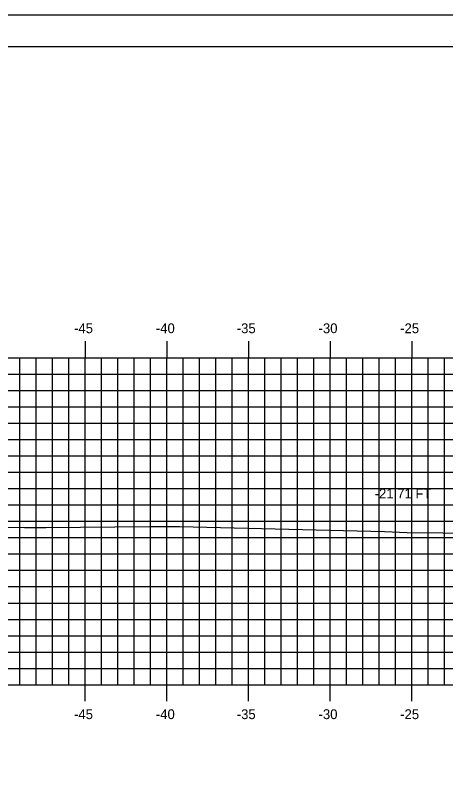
# Model space of a CAD drawing. Extents: x 1147633 to 1147803, y 608981 to 609091.
# Drawn here: x 1147667.17 to 1147693.53, y 609044.65 to 609091.28 of the extents above; entities that cross this region are included whole.
import ezdxf

# ---------------------------------------------------------------- set-up
doc = ezdxf.new("R2010")
doc.units = 0
for name, color, linetype in [('BORDER', 7, 'Continuous'), ('D_Text_Standard', 7, 'Continuous'), ('H_V ANNOTATION', 7, 'Continuous'), ('MAJOR', 7, 'Continuous'), ('MINOR', 7, 'Continuous'), ('PLOT BOUNDARY', 7, 'Continuous'), ('S_Roadway_Centerline', 7, 'Continuous')]:
    doc.layers.add(name, color=color, linetype=linetype)

msp = doc.modelspace()

# ---------------------------------------------------------------- linework, layer by layer
at = {"layer": 'BORDER'}
msp.add_lwpolyline([(1147641.454, 608984.335), (1147801.454, 608984.335), (1147801.454, 609089.335), (1147641.454, 609089.335)], close=True, dxfattribs=at)
at = {"layer": 'MAJOR'}
for p, q in [((1147671.454, 609071.337), (1147671.454, 609070.335)), ((1147676.454, 609071.337), (1147676.454, 609070.335)), ((1147681.454, 609071.337), (1147681.454, 609070.335)), ((1147686.454, 609071.337), (1147686.454, 609070.335)), ((1147691.454, 609071.337), (1147691.454, 609070.335)), ((1147646.454, 609070.335), (1147786.454, 609070.335)), ((1147646.454, 609070.335), (1147786.454, 609070.335)), ((1147671.454, 609050.335), (1147671.454, 609070.335)), ((1147676.454, 609050.335), (1147676.454, 609070.335)), ((1147681.454, 609050.335), (1147681.454, 609070.335)), ((1147686.454, 609050.335), (1147686.454, 609070.335)), ((1147691.454, 609050.335), (1147691.454, 609070.335)), ((1147646.454, 609065.335), (1147786.454, 609065.335)), ((1147646.454, 609060.335), (1147786.454, 609060.335)), ((1147646.454, 609055.335), (1147786.454, 609055.335)), ((1147646.454, 609050.335), (1147786.454, 609050.335)), ((1147646.454, 609050.335), (1147786.454, 609050.335)), ((1147671.454, 609049.333), (1147671.454, 609050.335)), ((1147676.454, 609049.333), (1147676.454, 609050.335)), ((1147681.454, 609049.333), (1147681.454, 609050.335)), ((1147686.454, 609049.333), (1147686.454, 609050.335)), ((1147691.454, 609049.333), (1147691.454, 609050.335))]:
    msp.add_line(p, q, dxfattribs=at)
at = {"layer": 'MINOR'}
for p, q in [((1147667.454, 609050.335), (1147667.454, 609070.335)), ((1147668.454, 609050.335), (1147668.454, 609070.335)), ((1147669.454, 609050.335), (1147669.454, 609070.335)), ((1147670.454, 609050.335), (1147670.454, 609070.335)), ((1147672.454, 609050.335), (1147672.454, 609070.335)), ((1147673.454, 609050.335), (1147673.454, 609070.335)), ((1147674.454, 609050.335), (1147674.454, 609070.335)), ((1147675.454, 609050.335), (1147675.454, 609070.335)), ((1147677.454, 609050.335), (1147677.454, 609070.335)), ((1147678.454, 609050.335), (1147678.454, 609070.335)), ((1147679.454, 609050.335), (1147679.454, 609070.335)), ((1147680.454, 609050.335), (1147680.454, 609070.335)), ((1147682.454, 609050.335), (1147682.454, 609070.335)), ((1147683.454, 609050.335), (1147683.454, 609070.335)), ((1147684.454, 609050.335), (1147684.454, 609070.335)), ((1147685.454, 609050.335), (1147685.454, 609070.335)), ((1147687.454, 609050.335), (1147687.454, 609070.335)), ((1147688.454, 609050.335), (1147688.454, 609070.335)), ((1147689.454, 609050.335), (1147689.454, 609070.335)), ((1147690.454, 609050.335), (1147690.454, 609070.335)), ((1147692.454, 609050.335), (1147692.454, 609070.335)), ((1147693.454, 609050.335), (1147693.454, 609070.335)), ((1147646.454, 609069.335), (1147786.454, 609069.335)), ((1147646.454, 609068.335), (1147786.454, 609068.335)), ((1147646.454, 609067.335), (1147786.454, 609067.335)), ((1147646.454, 609066.335), (1147786.454, 609066.335)), ((1147646.454, 609064.335), (1147786.454, 609064.335)), ((1147646.454, 609063.335), (1147786.454, 609063.335)), ((1147646.454, 609062.335), (1147786.454, 609062.335)), ((1147646.454, 609061.335), (1147786.454, 609061.335)), ((1147646.454, 609059.335), (1147786.454, 609059.335)), ((1147646.454, 609058.335), (1147786.454, 609058.335)), ((1147646.454, 609057.335), (1147786.454, 609057.335)), ((1147646.454, 609056.335), (1147786.454, 609056.335)), ((1147646.454, 609054.335), (1147786.454, 609054.335)), ((1147646.454, 609053.335), (1147786.454, 609053.335)), ((1147646.454, 609052.335), (1147786.454, 609052.335)), ((1147646.454, 609051.335), (1147786.454, 609051.335))]:
    msp.add_line(p, q, dxfattribs=at)
at = {"layer": 'PLOT BOUNDARY'}
msp.add_lwpolyline([(1147633.361, 608981.276), (1147803.361, 608981.276), (1147803.361, 609091.276), (1147633.361, 609091.276)], close=True, dxfattribs=at)
at = {"layer": 'S_Roadway_Centerline'}
msp.add_lwpolyline([(1147651.312, 609060.015), (1147651.694, 609060.012), (1147654.511, 609059.986), (1147665.339, 609059.998), (1147667.735, 609059.962), (1147669.05, 609059.952), (1147675.391, 609060.006), (1147677.225, 609060.005), (1147689.773, 609059.707), (1147691.167, 609059.648), (1147697.698, 609059.592)], dxfattribs=at)

# ---------------------------------------------------------------- texts
at = {"layer": 'D_Text_Standard'}
msp.add_text('-21.71 FT', height=0.6, dxfattribs=at).set_placement((1147689.176, 609061.726))
at = {"layer": 'H_V ANNOTATION'}
for s, p in [('-45', (1147670.772, 609071.835)), ('-40', (1147675.78, 609071.835)), ('-35', (1147680.734, 609071.835)), ('-30', (1147685.742, 609071.835)), ('-25', (1147690.739, 609071.835)), ('-45', (1147670.772, 609048.235)), ('-40', (1147675.78, 609048.235)), ('-35', (1147680.734, 609048.235)), ('-30', (1147685.742, 609048.235)), ('-25', (1147690.739, 609048.235))]:
    msp.add_text(s, height=0.6, dxfattribs=at).set_placement(p)

doc.saveas('drawing.dxf')
